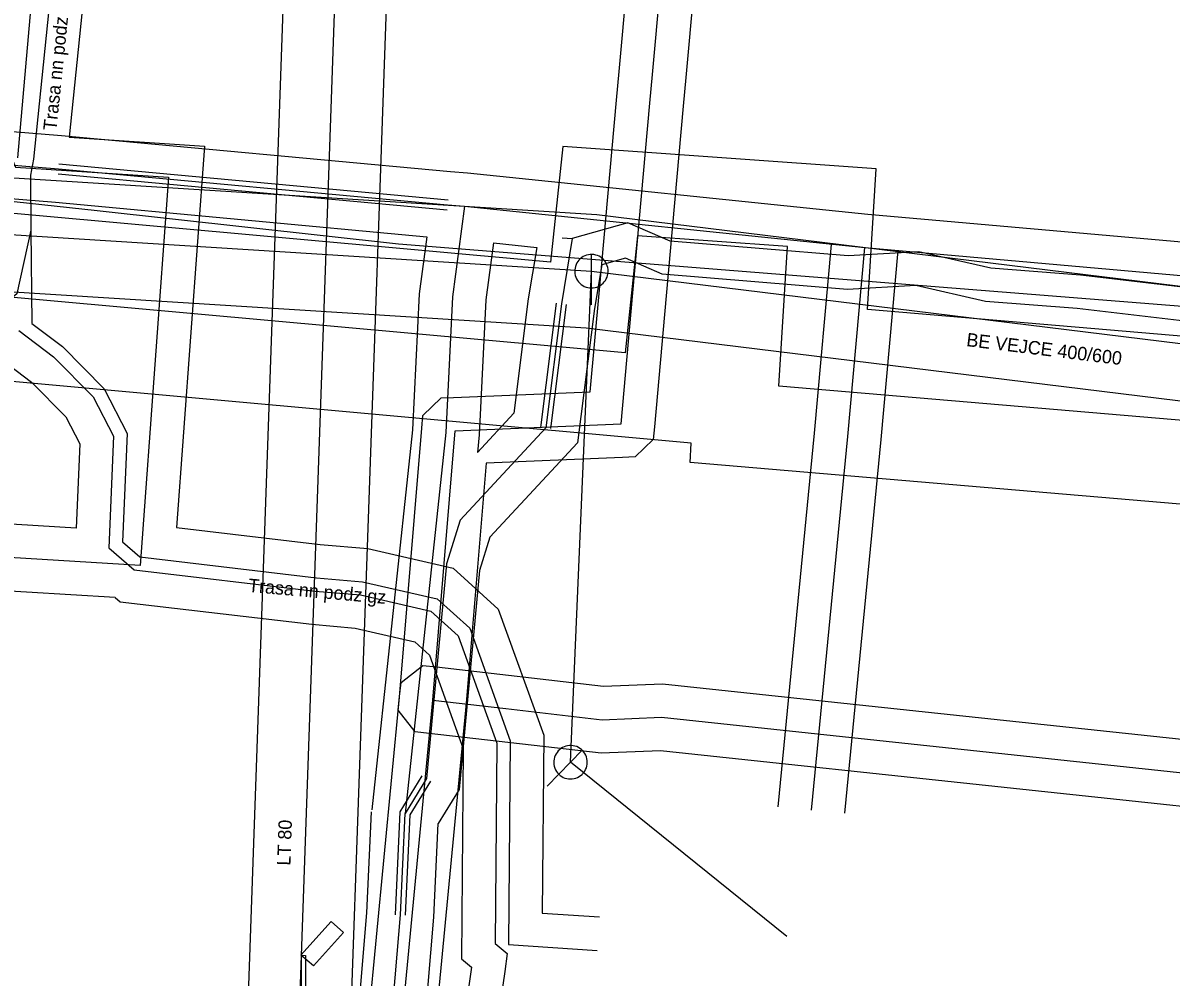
# Model space of a CAD drawing. Extents: x -762993 to -761845, y -975230 to -974501.
# Drawn here: x -762212.37 to -762178.08, y -975032.89 to -975004.4 of the extents above; entities that cross this region are included whole.
import ezdxf

# ---------------------------------------------------------------- set-up
doc = ezdxf.new("R2010")
doc.units = 0
for name, color, linetype in [('IS_CETIN_chranicka', 7, 'Continuous'), ('IS_CETIN_OP', 7, 'Continuous'), ('IS_CETIN_podzem metalika zam', 7, 'Continuous'), ('IS_CETIN_podzem optika zam', 7, 'Continuous'), ('IS_CETIN_podzem out of order', 7, 'Continuous'), ('IS_CEZ-D_anotace', 7, 'Continuous'), ('IS_CEZ-D_el vedeni NN podzem', 7, 'Continuous'), ('IS_CEZ-D_OP', 7, 'Continuous'), ('IS_CEZ-T_parovod', 7, 'Continuous'), ('IS_CEZ-T_parovod OP', 7, 'Continuous'), ('IS_DPmUL_VO lampy', 7, 'Continuous'), ('IS_GASNET_plyn NTL rad', 7, 'Continuous'), ('IS_GASNET_plyn OP', 7, 'Continuous'), ('IS_SCVK_kanalizace anotace', 7, 'Continuous'), ('IS_SCVK_kanalizace jednotna', 7, 'Continuous'), ('IS_SCVK_kanalizace OP', 7, 'Continuous'), ('IS_SCVK_kanalizace pripojky', 7, 'Continuous'), ('IS_SCVK_kanalizace znaky', 7, 'Continuous'), ('IS_SCVK_vodovod anotace', 7, 'Continuous'), ('IS_SCVK_vodovod OP', 7, 'Continuous'), ('IS_SCVK_vodovod privadec', 7, 'Continuous')]:
    doc.layers.add(name, color=color, linetype=linetype)

msp = doc.modelspace()

# ---------------------------------------------------------------- linework, layer by layer
at = {"layer": 'IS_CETIN_chranicka'}
for points in [[(-762211.296, -975008.601), (-762199.676, -975009.681)], [(-762211.324, -975008.899), (-762199.704, -975009.979)], [(-762196.909, -975016.471), (-762196.439, -975012.761)], [(-762196.611, -975016.509), (-762196.141, -975012.799)], [(-762201.25, -975031.023), (-762201.108, -975027.954), (-762200.448, -975026.881)], [(-762200.95, -975031.037), (-762200.812, -975028.046), (-762200.192, -975027.039)]]:
    msp.add_lwpolyline(points, dxfattribs=at)
at = {"layer": 'IS_CETIN_OP'}
for p, q in [((-762199.09, -975008.874), (-762187.135, -975010.105)), ((-762187.135, -975010.105), (-762159.034, -975012.594)), ((-762198.317, -975010.964), (-762197.027, -975011.097))]:
    msp.add_line(p, q, dxfattribs=at)
for points in [[(-762244.95, -975004.903), (-762232.795, -975005.994), (-762211.223, -975007.754), (-762199.605, -975008.834), (-762199.09, -975008.874)], [(-762246.119, -975006.806), (-762232.965, -975007.986), (-762211.397, -975009.746), (-762200.31, -975010.777)], [(-762200.31, -975010.777), (-762200.537, -975012.479), (-762200.737, -975016.542), (-762201.954, -975027.893)], [(-762198.317, -975010.964), (-762198.543, -975012.661), (-762198.743, -975016.698), (-762198.798, -975017.217)], [(-762197.027, -975011.097), (-762197.28, -975012.636), (-762197.712, -975016.046), (-762198.798, -975017.217)], [(-762189.815, -975027.804), (-762188.736, -975016.647), (-762188.226, -975011.01)], [(-762187.825, -975027.996), (-762186.744, -975016.833), (-762186.234, -975011.19)], [(-762105.752, -975019.119), (-762108.956, -975019.272), (-762116.886, -975018.639), (-762118.209, -975018.27), (-762121.344, -975018.26), (-762126.32, -975017.734), (-762130.385, -975017.267), (-762131.367, -975016.856), (-762135.732, -975016.981), (-762156.063, -975015.079), (-762157.972, -975014.627), (-762160.485, -975014.551), (-762162.638, -975014.765), (-762176.145, -975013.475), (-762180.887, -975012.925), (-762183.621, -975012.711), (-762185.704, -975012.236), (-762187.743, -975012.352), (-762193.286, -975011.893), (-762194.38, -975011.419), (-762195.086, -975011.619)], [(-762195.086, -975011.619), (-762195.3, -975012.924), (-762195.808, -975016.934), (-762198.423, -975019.754), (-762198.734, -975020.748), (-762199.346, -975027.285), (-762199.973, -975028.304)], [(-762202.829, -975039.678), (-762202.098, -975030.965), (-762201.959, -975027.954)], [(-762200.807, -975039.499), (-762200.102, -975031.095), (-762199.973, -975028.304)]]:
    msp.add_lwpolyline(points, dxfattribs=at)
at = {"layer": 'IS_CETIN_podzem metalika zam'}
for points in [[(-762105.8, -975018.12), (-762108.94, -975018.27), (-762116.71, -975017.65), (-762118.07, -975017.27), (-762121.29, -975017.26), (-762126.21, -975016.74), (-762130.13, -975016.29), (-762131.18, -975015.85), (-762135.7, -975015.98), (-762155.9, -975014.09), (-762157.84, -975013.63), (-762160.52, -975013.55), (-762162.64, -975013.76), (-762176.04, -975012.48), (-762180.79, -975011.93), (-762183.47, -975011.72), (-762185.62, -975011.23), (-762187.73, -975011.35), (-762193.04, -975010.91), (-762194.31, -975010.36), (-762195.97, -975010.83)], [(-762195.97, -975010.83), (-762196.29, -975012.78), (-762196.76, -975016.49), (-762199.31, -975019.24), (-762199.72, -975020.55), (-762200.32, -975026.96), (-762200.96, -975028)], [(-762196.27, -975010.81), (-762195.97, -975010.83)], [(-762188.82, -975027.9), (-762187.74, -975016.74), (-762187.23, -975011.1)]]:
    msp.add_lwpolyline(points, dxfattribs=at)
at = {"layer": 'IS_CETIN_podzem optika zam'}
for points in [[(-762246.03, -975005.81), (-762232.88, -975006.99), (-762211.31, -975008.75), (-762199.69, -975009.83), (-762199.18, -975009.87)], [(-762199.18, -975009.87), (-762199.54, -975012.57), (-762199.74, -975016.62), (-762200.96, -975028)], [(-762199.18, -975009.87), (-762187.23, -975011.1)], [(-762187.23, -975011.1), (-762160.59, -975013.46)], [(-762201.82, -975039.61), (-762201.1, -975031.03), (-762200.96, -975028)]]:
    msp.add_lwpolyline(points, dxfattribs=at)
at = {"layer": 'IS_CETIN_podzem out of order'}
msp.add_lwpolyline([(-762250.2, -975005.66), (-762210.15, -975010), (-762201.16, -975010.99), (-762121.16, -975017.35), (-762071.23, -975020.85), (-762043.47, -975023.41)], dxfattribs=at)
at = {"layer": 'IS_CEZ-D_el vedeni NN podzem'}
for points in [[(-762193.524, -974995.956), (-762193.614, -974996.71), (-762193.822, -974998.453), (-762211.362, -974996.973), (-762212.503, -974999.99), (-762212.93, -975007.897), (-762212.59, -975008.699), (-762208.023, -975009.002), (-762208.841, -975020.191), (-762208.871, -975020.599), (-762216.194, -975020.151), (-762233.978, -975019.299), (-762252.877, -975017.917), (-762257.832, -975017.547), (-762262.774, -975017.178), (-762264.709, -975017.162), (-762266.642, -975017.146), (-762269.935, -975017.363)], [(-762193.524, -974995.955), (-762194.408, -974995.878), (-762194.761, -974999.565), (-762195.389, -975000.774), (-762196.355, -975000.599), (-762196.501, -974999.292), (-762199.187, -974999.2), (-762199.452, -975000.113), (-762202.537, -974999.841), (-762211.266, -974999.16), (-762211.822, -975000.258), (-762212.529, -975008.421)], [(-762211.14, -974999.72), (-762211.22, -975000.29), (-762212.06, -975008.46), (-762212.15, -975008.94), (-762212.14, -975010.58)], [(-762212.14, -975010.58), (-762212.55, -975012.48), (-762213.16, -975012.98), (-762219.59, -975012.4), (-762219.66, -975013.03), (-762219.86, -975015.66), (-762219.94, -975016.9), (-762219.77, -975019.1), (-762219.49, -975021.35), (-762218.75, -975022.51), (-762217.94, -975024.34), (-762217.91, -975026.5), (-762218.29, -975031.99), (-762219.04, -975038.13)], [(-762212.14, -975010.58), (-762212.11, -975013.37), (-762211.19, -975014.06), (-762209.95, -975015.32), (-762209.26, -975016.65), (-762209.4, -975019.89), (-762208.88, -975020.34), (-762203.6, -975020.96), (-762202.23, -975021.08), (-762200, -975021.59), (-762199.03, -975022.47), (-762197.82, -975025.83), (-762197.87, -975031.91), (-762195.22, -975032.09)], [(-762212.495, -975013.581), (-762211.454, -975014.362), (-762210.277, -975015.558), (-762209.664, -975016.739), (-762209.808, -975020.066), (-762209.049, -975020.723), (-762203.641, -975021.358), (-762202.292, -975021.476), (-762200.191, -975021.957), (-762199.373, -975022.699), (-762198.221, -975025.898), (-762198.27, -975031.88), (-762197.91, -975032.187), (-762197.984, -975032.721), (-762198.14, -975033.81)]]:
    msp.add_lwpolyline(points, dxfattribs=at)
at = {"layer": 'IS_CEZ-D_OP'}
msp.add_line((-762210.265, -975000.775), (-762210.987, -975007.803), dxfattribs=at)
for points in [[(-762210.987, -975007.803), (-762206.952, -975008.071), (-762207.785, -975019.462)], [(-762210.784, -975019.48), (-762216.14, -975019.152), (-762233.918, -975018.301), (-762252.803, -975016.92), (-762257.758, -975016.55), (-762262.733, -975016.178), (-762264.701, -975016.162), (-762266.671, -975016.146), (-762270.081, -975016.37), (-762273.062, -975017.056), (-762274.852, -975017.621), (-762277.427, -975019.146), (-762279.613, -975021.175), (-762281.167, -975023.071), (-762282.764, -975025.331), (-762283.845, -975028.749), (-762293.788, -975024.216), (-762299.936, -975020.663), (-762307.64, -975012.706), (-762307.985, -975012.349)], [(-762209.615, -975021.555), (-762216.248, -975021.15), (-762234.038, -975020.297), (-762252.951, -975018.914), (-762257.906, -975018.544), (-762262.815, -975018.178), (-762264.717, -975018.162), (-762266.613, -975018.146), (-762269.789, -975018.356), (-762272.536, -975018.988), (-762274.03, -975019.459), (-762276.223, -975020.758), (-762278.153, -975022.549), (-762279.575, -975024.283), (-762280.95, -975026.231), (-762282.619, -975031.505), (-762294.706, -975025.996), (-762301.178, -975022.255), (-762309.078, -975014.096), (-762309.618, -975013.538), (-762311.559, -975013.102)], [(-762213.47, -975013.956), (-762213.458, -975014.109), (-762212.114, -975015.117), (-762211.095, -975016.152), (-762210.675, -975016.963), (-762210.784, -975019.48)], [(-762207.785, -975019.462), (-762203.498, -975019.965), (-762202.074, -975020.09), (-762199.522, -975020.674), (-762198.174, -975021.897), (-762196.819, -975025.659), (-762196.862, -975030.976), (-762195.152, -975031.092)], [(-762209.615, -975021.555), (-762209.471, -975021.68), (-762203.743, -975022.353), (-762202.448, -975022.466), (-762200.669, -975022.873), (-762200.229, -975023.272), (-762199.222, -975026.069), (-762199.274, -975032.338), (-762198.976, -975032.592), (-762199.135, -975033.703)]]:
    msp.add_lwpolyline(points, dxfattribs=at)
at = {"layer": 'IS_CEZ-T_parovod'}
msp.add_lwpolyline([(-761997.94, -975128.34), (-762040.63, -975080.79), (-762092.91, -975023.16), (-762093.78, -975023), (-762095.1, -975022.88), (-762139.5, -975019.26), (-762139.25, -975015.36), (-762142, -975015.09), (-762142.45, -975019.26), (-762189.8, -975015.24), (-762189.54, -975011.07), (-762194.02, -975010.75), (-762194.39, -975014.25), (-762239.28, -975010.18), (-762239.14, -975006.45), (-762242.94, -975006.24), (-762243.22, -975009.53), (-762252.6, -975008.69), (-762274.12, -975007.08), (-762277.86, -975004.82)], dxfattribs=at)
at = {"layer": 'IS_CEZ-T_parovod OP'}
for points in [[(-761996.08, -975126.67), (-762038.774, -975079.115), (-762091.626, -975020.854), (-762093.44, -975020.521), (-762094.885, -975020.389), (-762136.848, -975016.968), (-762136.601, -975013.108), (-762144.22, -975012.36), (-762144.673, -975016.562), (-762187.153, -975012.956), (-762186.891, -975008.753), (-762196.252, -975008.084), (-762196.617, -975011.538), (-762236.693, -975007.904), (-762236.55, -975004.089), (-762245.225, -975003.61), (-762245.498, -975006.816), (-762252.395, -975006.198), (-762273.338, -975004.632), (-762275.663, -975003.227)], [(-761999.8, -975130.01), (-762042.486, -975082.465), (-762094.187, -975025.473), (-762095.315, -975025.371), (-762140.2, -975021.711), (-762140.227, -975021.958), (-762192.447, -975017.524), (-762192.411, -975016.94), (-762241.867, -975012.456), (-762241.856, -975012.162), (-762252.805, -975011.182), (-762274.902, -975009.528), (-762278.275, -975007.49)]]:
    msp.add_lwpolyline(points, dxfattribs=at)
at = {"layer": 'IS_DPmUL_VO lampy'}
for points in [[(-762203.164, -975031.224), (-762202.794, -975031.554), (-762203.694, -975032.554), (-762204.074, -975032.234)], [(-762204.054, -975032.234), (-762203.934, -975032.244), (-762203.934, -975034.884), (-762204.054, -975034.874)]]:
    msp.add_lwpolyline(points, close=True, dxfattribs=at)
at = {"layer": 'IS_GASNET_plyn NTL rad'}
for points in [[(-762209.373, -975122.133), (-762207.18, -975102.52), (-762206.04, -975089.29), (-762203.68, -975062.33), (-762201.05, -975034.18), (-762200.13, -975024.62), (-762199.466, -975016.577), (-762194.51, -975016.37), (-762194.157, -975012.456), (-762193.646, -975006.792), (-762193.568, -975005.933), (-762193.101, -975000.758), (-762193.07, -975000.41)], [(-762200.13, -975024.62), (-762197.953, -975024.87), (-762195.07, -975025.2), (-762193.3, -975025.13), (-762162.45, -975028.42), (-762149.72, -975029.5), (-762136.08, -975030.63)]]:
    msp.add_lwpolyline(points, dxfattribs=at)
at = {"layer": 'IS_GASNET_plyn OP'}
for points in [[(-762202.046, -975034.086), (-762201.126, -975024.531), (-762200.463, -975016.495), (-762200.432, -975016.118), (-762199.886, -975015.594), (-762199.508, -975015.578), (-762195.427, -975015.407), (-762195.153, -975012.366), (-762194.642, -975006.702), (-762194.564, -975005.843), (-762194.097, -975000.669)], [(-762192.105, -975000.847), (-762192.572, -975006.023), (-762192.65, -975006.882), (-762193.161, -975012.546), (-762193.514, -975016.46), (-762193.548, -975016.835), (-762194.092, -975017.354), (-762194.468, -975017.369), (-762198.542, -975017.539), (-762199.134, -975024.709), (-762200.054, -975034.274)]]:
    msp.add_lwpolyline(points, dxfattribs=at)
msp.add_lwpolyline([(-762200.428, -975023.58), (-762200.016, -975023.627), (-762195.033, -975024.198), (-762193.267, -975024.128), (-762162.355, -975027.424), (-762149.636, -975028.503), (-762135.997, -975029.633), (-762135.584, -975029.667), (-762135.049, -975030.3), (-762135.083, -975030.713), (-762135.117, -975031.126), (-762135.75, -975031.661), (-762136.163, -975031.627), (-762149.804, -975030.497), (-762162.545, -975029.416), (-762193.333, -975026.132), (-762195.107, -975026.202), (-762200.244, -975025.613), (-762200.655, -975025.566), (-762201.17, -975024.918), (-762201.123, -975024.506), (-762201.076, -975024.095)], close=True, dxfattribs=at)
at = {"layer": 'IS_SCVK_kanalizace jednotna'}
for points in [[(-762233.263, -975009.418), (-762195.393, -975011.808)], [(-762195.393, -975011.808), (-762167.023, -975015.287)]]:
    msp.add_lwpolyline(points, dxfattribs=at)
at = {"layer": 'IS_SCVK_kanalizace OP'}
for p, q in [((-762233.103, -975007.725), (-762195.236, -975010.115)), ((-762195.236, -975010.115), (-762166.816, -975013.6)), ((-762233.423, -975011.111), (-762195.55, -975013.501)), ((-762195.55, -975013.501), (-762167.23, -975016.974))]:
    msp.add_line(p, q, dxfattribs=at)
at = {"layer": 'IS_SCVK_kanalizace pripojky'}
for points in [[(-762196.017, -975026.471), (-762195.393, -975011.808)], [(-762189.555, -975031.671), (-762196.017, -975026.472)]]:
    msp.add_lwpolyline(points, dxfattribs=at)
at = {"layer": 'IS_SCVK_kanalizace znaky'}
for points in [[(-762194.893, -975011.808), (-762194.895, -975011.753), (-762194.905, -975011.7), (-762194.92, -975011.647), (-762194.939, -975011.596), (-762194.966, -975011.548), (-762194.997, -975011.503), (-762195.033, -975011.461), (-762195.073, -975011.424), (-762195.117, -975011.391), (-762195.164, -975011.364), (-762195.214, -975011.341), (-762195.266, -975011.325), (-762195.319, -975011.314), (-762195.374, -975011.309), (-762195.429, -975011.31), (-762195.483, -975011.317), (-762195.537, -975011.329), (-762195.588, -975011.348), (-762195.637, -975011.372), (-762195.683, -975011.401), (-762195.726, -975011.436), (-762195.765, -975011.474), (-762195.799, -975011.517), (-762195.829, -975011.563), (-762195.853, -975011.612), (-762195.871, -975011.664), (-762195.884, -975011.717), (-762195.891, -975011.771), (-762195.893, -975011.826), (-762195.888, -975011.881), (-762195.877, -975011.934), (-762195.86, -975011.986), (-762195.838, -975012.036), (-762195.811, -975012.084), (-762195.778, -975012.128), (-762195.741, -975012.168), (-762195.699, -975012.204), (-762195.654, -975012.235), (-762195.606, -975012.261), (-762195.555, -975012.281), (-762195.503, -975012.296), (-762195.449, -975012.305), (-762195.394, -975012.308), (-762195.339, -975012.305), (-762195.285, -975012.296), (-762195.233, -975012.282), (-762195.182, -975012.261), (-762195.133, -975012.235), (-762195.088, -975012.204), (-762195.047, -975012.169), (-762195.009, -975012.128), (-762194.976, -975012.084), (-762194.949, -975012.038), (-762194.927, -975011.988), (-762194.91, -975011.936), (-762194.899, -975011.882), (-762194.894, -975011.827), (-762194.893, -975011.808)], [(-762195.393, -975012.808), (-762195.393, -975011.308)], [(-762196.718, -975027.185), (-762195.667, -975026.114)], [(-762195.66, -975026.821), (-762195.624, -975026.78), (-762195.593, -975026.736), (-762195.566, -975026.687), (-762195.545, -975026.637), (-762195.53, -975026.584), (-762195.52, -975026.53), (-762195.517, -975026.476), (-762195.52, -975026.421), (-762195.528, -975026.367), (-762195.542, -975026.314), (-762195.562, -975026.263), (-762195.588, -975026.215), (-762195.618, -975026.169), (-762195.654, -975026.128), (-762195.694, -975026.09), (-762195.738, -975026.057), (-762195.784, -975026.028), (-762195.834, -975026.006), (-762195.886, -975025.989), (-762195.939, -975025.977), (-762195.994, -975025.972), (-762196.049, -975025.972), (-762196.104, -975025.979), (-762196.157, -975025.991), (-762196.208, -975026.009), (-762196.258, -975026.033), (-762196.304, -975026.062), (-762196.347, -975026.096), (-762196.386, -975026.134), (-762196.421, -975026.177), (-762196.451, -975026.222), (-762196.475, -975026.271), (-762196.494, -975026.322), (-762196.508, -975026.375), (-762196.515, -975026.43), (-762196.517, -975026.484), (-762196.513, -975026.539), (-762196.502, -975026.593), (-762196.486, -975026.645), (-762196.464, -975026.695), (-762196.437, -975026.743), (-762196.405, -975026.787), (-762196.368, -975026.828), (-762196.327, -975026.864), (-762196.282, -975026.895), (-762196.234, -975026.922), (-762196.183, -975026.943), (-762196.131, -975026.958), (-762196.077, -975026.967), (-762196.022, -975026.971), (-762195.968, -975026.969), (-762195.914, -975026.96), (-762195.861, -975026.946), (-762195.81, -975026.926), (-762195.761, -975026.9), (-762195.716, -975026.87), (-762195.674, -975026.834), (-762195.66, -975026.821)]]:
    msp.add_lwpolyline(points, dxfattribs=at)
at = {"layer": 'IS_SCVK_vodovod OP'}
for points in [[(-762204.543, -975002.001), (-762206.54, -975058.879), (-762207.836, -975077.307)], [(-762201.469, -975002.227), (-762203.464, -975059.041), (-762204.764, -975077.523)]]:
    msp.add_lwpolyline(points, dxfattribs=at)
at = {"layer": 'IS_SCVK_vodovod privadec'}
msp.add_lwpolyline([(-762203.006, -975002.114), (-762205.002, -975058.96), (-762206.3, -975077.415)], dxfattribs=at)

# ---------------------------------------------------------------- texts
at = {"layer": 'IS_CEZ-D_anotace'}
for rotation, p in [(84.1298, (-762211.371, -975007.621)), (354.9942, (-762205.657, -975021.383))]:
    msp.add_text('Trasa nn podz gz', height=0.4, rotation=rotation, dxfattribs=at).set_placement(p)
at = {"layer": 'IS_SCVK_kanalizace anotace'}
msp.add_text('BE VEJCE 400/600', height=0.4, rotation=353, dxfattribs=at).set_placement((-762184.211, -975014.043))
at = {"layer": 'IS_SCVK_vodovod anotace'}
msp.add_text('LT 80 ', height=0.4, rotation=88, dxfattribs=at).set_placement((-762204.384, -975029.562))

doc.saveas('drawing.dxf')
